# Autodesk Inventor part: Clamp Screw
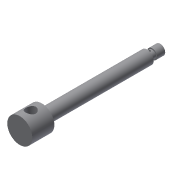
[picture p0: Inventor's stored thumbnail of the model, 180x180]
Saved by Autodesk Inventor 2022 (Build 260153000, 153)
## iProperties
Created: 2002-02
Part Number: Clamp Screw
Document SubType Name: Modeling
Designer: ***
Density: 1 g/cm^3
Material: Generic
Mass: 23.4191 g
Surface Area: 81.8482 cm^2
Volume: 23.4191 cm^3
Appearance: Default
Control State: 0
Master: False
Checked Out: False
Shininess: 77.0
Length Units: 11269
Angle Units: 11279
Time Units: 11290
Mass Units: 11283
Length Display Precision: 3
Angle Display Precision: 2
Density: 0.0
Volumn: 0.0
Area: 0.0
PropertySet Name: Model Information
Author: ***
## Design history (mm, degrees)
sketch "Sketch1"
  geometry: L1 (0, 140)-(5, 140); L2 (5, 140)-(5, 132); L3 (5, 132)-(4, 132); L4 (4, 132)-(4, 127); L5 (4, 127)-(6.5, 127); L6 (6.5, 127)-(6.5, 25); L7 (6.5, 25)-(4, 25); L8 (4, 25)-(4, 22); L9 (4, 22)-(12.5, 22); L10 (12.5, 22)-(12.5, 0); L11 (12.5, 0)-(0, 0); L12 (0, 0)-(0, 140)
  constraints: 24 end point, 10 parallel, 1 horizontal, 1 perpendicular
  dimensions: "d0" = 10 diameter of L2 L12; "d1" = 8 diameter of L4 L12; "d2" = 13 diameter of L6 L12; "d3" = 8 diameter of L7.end L12; "d4" = 25 diameter of L10 L12; "d5" = 3 distance from line of L7.end L9; "d6" = 8 distance of L1.end L2.end; "d7" = 13 vertical distance of L1.end L5.end; "d8" = 22 distance of L9.end L10.end; "d10" = 102 distance of L5.end L6.end
revolve "Revolution1" sketch "Sketch1" stored, may be unused: angle "d11" = 90 deg
sketch "Sketch3"
  geometry: L1 (-12.5, 0)-(12.5, 0) reference; C1 r 5 at (-0.113, 11)
  constraints: 1 centre point
  dimensions: "d13" = 10 diameter of C1; "d14" = 11 distance from line of L1 C1.centre
extrude "Extrusion1" cut sketch "Sketch3" extent not by distance; stored distance "d15" = 10; taper "d16" = 0 deg
sketch "Sketch4"
  geometry: L1 (0, 138.841)-(0, 0); L2 (-12.5, 0)-(12.5, 0) reference; L3 (-5, 140)-(5, 140) reference; C1 r 1 at (0, 129.5)
  constraints: 2 end point, 1 centre point, 1 point on line, 1 vertical
  dimensions: "d17" = 2 diameter of C1; "d18" = 10.5 distance from line of L3 C1.centre
extrude "Extrusion2" cut sketch "Sketch4" stored distance "d19" = 10; taper "d20" = 0 deg
body "Solid1"
